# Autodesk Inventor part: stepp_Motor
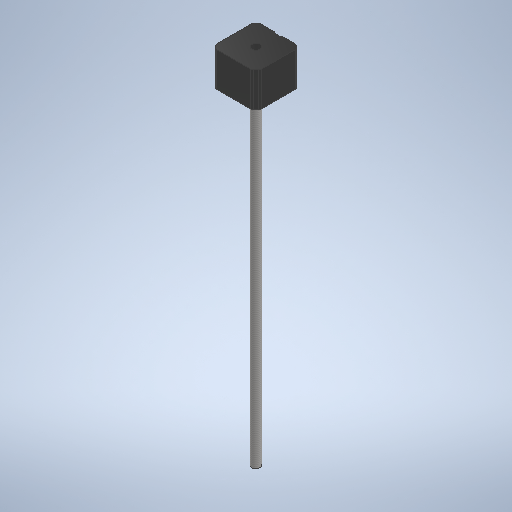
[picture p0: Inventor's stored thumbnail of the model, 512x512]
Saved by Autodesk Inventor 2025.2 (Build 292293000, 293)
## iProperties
Created: 2025-04
Part Number: stepp_Motor
Material: Generic
Document SubType Name: Modeling
Designer: Jarni
Density: 1 g/cm^3
Appearance: Default
Author: Jarni
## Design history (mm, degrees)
sketch "Sketch1"
  geometry: C1 r 4 at (0, 0); 1 further point
  constraints: 1 centre point, 1 coincident
  dimensions: "d0" = 8 diameter of C1
extrude "Extrusion1" new body sketch "Sketch1" distance "d1" = 310; taper "d2" = 0 deg
thread "Thread1" dims "d3" = 310, "d4" = 0
sketch "Sketch2"
  geometry: L1 (20.9, -20.9)-(-20.9, -20.9); L2 (-20.9, -20.9)-(-20.9, 20.9); L3 (-20.9, 20.9)-(20.9, 20.9); L4 (20.9, 20.9)-(20.9, -20.9); L5 (20.9, -20.9)-(-20.9, 20.9); L6 (-20.9, -20.9)-(20.9, 20.9); C1 r 4 at (0, 0) reference; 1 further point
  constraints: 12 end point, 2 midpoint, 2 parallel, 1 horizontal, 1 perpendicular
  dimensions: "d5" = 41.8 distance of L1.end L2.end; "d6" = 41.8 distance of L2.end L3.end
extrude "Extrusion2" join sketch "Sketch2" distance "d7" = 32.56; taper "d8" = 0 deg
sketch "Sketch3"
  geometry: L1 (-15.5, 15.5)-(15.5, 15.5); L2 (15.5, 15.5)-(15.5, -15.5); L3 (15.5, -15.5)-(-15.5, -15.5); L4 (-15.5, -15.5)-(-15.5, 15.5); L5 (-15.5, 15.5)-(15.5, -15.5); L6 (15.5, 15.5)-(-15.5, -15.5); C1 r 1.5 at (15.5, 15.5); C2 r 1.5 at (15.5, -15.5); C3 r 1.5 at (-15.5, -15.5); C4 r 1.5 at (-15.5, 15.5); 1 further point
  constraints: 12 end point, 4 centre point, 4 coincident, 2 midpoint, 2 parallel, 1 horizontal, 1 perpendicular
  dimensions: "d9" = 31 distance of L2.end L3.end; "d10" = 31 distance of L1.end L2.end; "d11" = 3 diameter of C1; "d12" = 3 diameter of C2; "d13" = 3 diameter of C3; "d14" = 3 diameter of C4
extrude "Extrusion3" cut sketch "Sketch3" distance "d15" = 5; taper "d16" = 0 deg
sketch "Sketch4"
  geometry: L1 (-20.9, 20.9)-(20.9, 20.9) reference; L2 (-20.9, -20.9)-(-20.9, 20.9) reference; L3 (20.9, -20.9)-(-20.9, -20.9) reference; L4 (20.9, 20.9)-(20.9, -20.9) reference; L5 (-20.9, 20.9)-(20.9, 20.9) reference; L6 (-20.9, -20.9)-(-20.9, 20.9) reference; L7 (20.9, 20.9)-(20.9, -20.9) reference; L8 (20.9, -17)-(17, -20.9); L9 (20.9, -20.9)-(-20.9, -20.9) reference; L10 (-17, -20.9)-(-20.9, -17); L11 (-17, 20.9)-(-20.9, 17); L12 (17, 20.9)-(20.9, 17); C1 r 1.5 at (-15.5, -15.5) reference; C2 r 1.5 at (15.5, -15.5) reference; C3 r 1.5 at (-15.5, 15.5) reference; C4 r 1.5 at (15.5, 15.5) reference; C5 r 4 at (0, 0) reference; 10 further points
  constraints: 8 end point, 8 point on line
  dimensions: "d17" = 34 distance of L8.start L12.end; "d18" = 34 distance of L10.start L8.end; "d19" = 34 distance of L11.end L10.end; "d20" = 34 distance of L12.start L11.start; "d21" = 3.9 distance of L3.start L8.start; "d22" = 3.9 distance of L8.end L3.start; "d23" = 3.9 distance of L1.end L12.start; "d24" = 3.9 distance of L1.start L11.end
extrude "Extrusion4" cut sketch "Sketch4" distance "d25" = 40; taper "d26" = 0 deg
fillet "Fillet1" dims "d27" = 2
sketch "Sketch5"
  geometry: C1 r 11 at (0, 0); 1 further point
  constraints: 1 centre point, 1 coincident
  dimensions: "d28" = 22 diameter of C1
extrude "Extrusion5" join sketch "Sketch5" distance "d29" = 2.4; taper "d30" = 0 deg
sketch "Sketch6"
  geometry: L1 (32.343, 32.56)-(0, 32.56) reference; L2 (12.923, 32.56)-(19.443, 32.56); L3 (19.443, 32.56)-(19.443, 26.04); L4 (19.443, 26.04)-(12.923, 26.04); L5 (12.923, 26.04)-(12.923, 32.56); L6 (32.343, 32.56)-(32.343, 0) reference; 2 further points
  constraints: 8 end point, 2 parallel, 1 horizontal, 1 perpendicular, 1 point on line
  dimensions: "d31" = 6.52 distance of L3.end L4.end; "d32" = 6.52 distance of L2.end L3.end; "d33" = 12.9 distance between parallel lines of L6 L3
extrude "Extrusion6" cut sketch "Sketch6" distance "d34" = 1; taper "d35" = 0 deg
body "Solid1"
node "Projected Loop1"
